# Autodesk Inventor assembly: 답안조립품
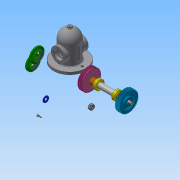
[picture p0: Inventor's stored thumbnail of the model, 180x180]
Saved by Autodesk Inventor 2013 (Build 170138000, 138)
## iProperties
Created: 2019-11
Part Number: 답안조립품
Document SubType Name: Assembly
Designer: Administrator
Author: Administrator
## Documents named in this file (14)
- C:\Users\Administrator\Desktop\491104V1047\답안조립품.iam
- C:\Users\Administrator\Desktop\491104V1047\V-벨트풀리.ipt
- V-벨트풀리.ipt
- C:\Users\Administrator\Desktop\491104V1047\너트 M12x1.25.ipt
- C:\Users\Administrator\Desktop\491104V1047\베어링 6203.ipt
- C:\Users\Administrator\Desktop\491104V1047\본체.ipt
- C:\Users\Administrator\Desktop\491104V1047\볼트 M4.ipt
- C:\Users\Administrator\Desktop\491104V1047\부시.ipt
- C:\Users\Administrator\Desktop\491104V1047\스퍼기어.ipt
- C:\Users\Administrator\Desktop\491104V1047\오일 실 26 38 8.ipt
- C:\Users\Administrator\Desktop\491104V1047\와셔 12x24.ipt
- C:\Users\Administrator\Desktop\491104V1047\축.ipt
- C:\Users\Administrator\Desktop\491104V1047\커버.ipt
- C:\Users\Administrator\Desktop\491104V1047\키 5x5x12.ipt
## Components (1 placed, 1 different names)
1. V-벨트풀리:1
